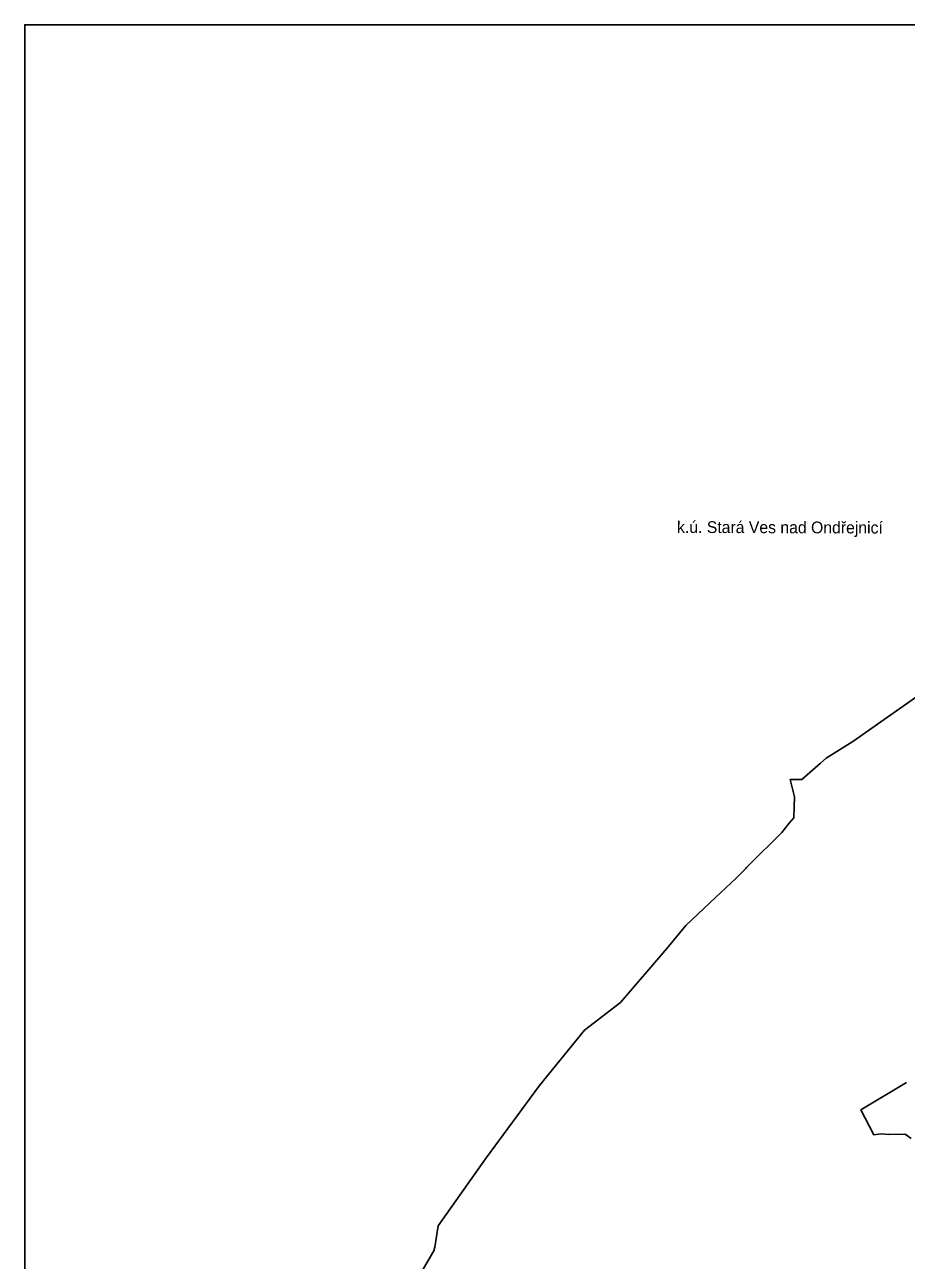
# Model space of a CAD drawing. Extents: x -478440 to -472455, y -1118045 to -1113755.
# Drawn here: x -478440 to -476944, y -1115899 to -1113800 of the extents above; entities that cross this region are included whole.
import ezdxf

# ---------------------------------------------------------------- set-up
doc = ezdxf.new("R2010")
doc.units = 0
for name, color, linetype in [('hranice kú', 7, 'Continuous'), ('Implicitní', 7, 'Continuous'), ('ObPÚ', 7, 'Continuous'), ('okolní k_ú_', 7, 'Continuous')]:
    doc.layers.add(name, color=color, linetype=linetype)

msp = doc.modelspace()

# ---------------------------------------------------------------- linework, layer by layer
at = {"layer": 'hranice kú'}
for p, q in [((-476889.8, -1114915.9), (-477034.1, -1115017.7)), ((-477034.1, -1115017.7), (-477047.8, -1115026.2)), ((-477047.8, -1115026.2), (-477079.5, -1115046.1)), ((-477098.4, -1115062.6), (-477121, -1115082.3)), ((-477089.2, -1115054.5), (-477098.4, -1115062.6)), ((-477079.5, -1115046.1), (-477089.2, -1115054.5)), ((-477121, -1115082.3), (-477141, -1115082)), ((-477141, -1115082), (-477133.6, -1115111.5)), ((-477133.6, -1115111.5), (-477134.2, -1115129.3)), ((-477134.7, -1115147.1), (-477142.3, -1115156.6)), ((-477134.2, -1115129.3), (-477134.7, -1115147.1)), ((-477142.3, -1115156.6), (-477155, -1115172.4)), ((-477155, -1115172.4), (-477210.7, -1115227.9)), ((-477210.7, -1115227.9), (-477214.6, -1115231.9)), ((-477233.1, -1115250.4), (-477267, -1115282.3)), ((-477229.4, -1115246.9), (-477233.1, -1115250.4)), ((-477216.6, -1115233.9), (-477229.4, -1115246.9)), ((-477214.6, -1115231.9), (-477216.6, -1115233.9)), ((-477267, -1115282.3), (-477317.9, -1115330.4)), ((-477317.9, -1115330.4), (-477350, -1115369.3)), ((-477350, -1115369.3), (-477428.5, -1115460.9)), ((-477428.5, -1115460.9), (-477490.1, -1115508.2)), ((-477490.1, -1115508.2), (-477566.2, -1115601.8)), ((-477566.2, -1115601.8), (-477658.2, -1115726.7)), ((-477658.2, -1115726.7), (-477738.5, -1115840.6)), ((-477738.5, -1115840.6), (-477743.9, -1115876.8)), ((-477743.9, -1115876.8), (-477745.7, -1115882.6)), ((-477745.7, -1115882.6), (-477792.7, -1115963.5))]:
    msp.add_line(p, q, dxfattribs=at)
at = {"layer": 'Implicitní'}
msp.add_lwpolyline([(-478440.1, -1118000.1), (-472500.1, -1118000.1), (-472500.1, -1113800.1), (-478440.1, -1113800.1)], close=True, dxfattribs=at)
at = {"layer": 'ObPÚ'}
for p, q in [((-476889.8, -1114915.9), (-477034.1, -1115017.7)), ((-477034.1, -1115017.7), (-477047.8, -1115026.2)), ((-477047.8, -1115026.2), (-477079.5, -1115046.1)), ((-477098.4, -1115062.6), (-477121, -1115082.3)), ((-477089.2, -1115054.5), (-477098.4, -1115062.6)), ((-477079.5, -1115046.1), (-477089.2, -1115054.5)), ((-477121, -1115082.3), (-477141, -1115082)), ((-477141, -1115082), (-477133.6, -1115111.5)), ((-477133.6, -1115111.5), (-477134.2, -1115129.3)), ((-477134.7, -1115147.1), (-477142.3, -1115156.6)), ((-477134.2, -1115129.3), (-477134.7, -1115147.1)), ((-477142.3, -1115156.6), (-477155, -1115172.4)), ((-477155, -1115172.4), (-477210.7, -1115227.9)), ((-477210.7, -1115227.9), (-477214.6, -1115231.9)), ((-477233.1, -1115250.4), (-477267, -1115282.3)), ((-477229.4, -1115246.9), (-477233.1, -1115250.4)), ((-477216.6, -1115233.9), (-477229.4, -1115246.9)), ((-477214.6, -1115231.9), (-477216.6, -1115233.9)), ((-477267, -1115282.3), (-477317.9, -1115330.4)), ((-477317.9, -1115330.4), (-477350, -1115369.3)), ((-477350, -1115369.3), (-477428.5, -1115460.9)), ((-477428.5, -1115460.9), (-477490.1, -1115508.2)), ((-477490.1, -1115508.2), (-477566.2, -1115601.8)), ((-477566.2, -1115601.8), (-477658.2, -1115726.7)), ((-477658.2, -1115726.7), (-477738.5, -1115840.6)), ((-477738.5, -1115840.6), (-477743.9, -1115876.8)), ((-477743.9, -1115876.8), (-477745.7, -1115882.6)), ((-477745.7, -1115882.6), (-477792.7, -1115963.5))]:
    msp.add_line(p, q, dxfattribs=at)
msp.add_lwpolyline([(-476935.6, -1115692.1), (-476945.3, -1115684.7), (-476973.5, -1115685.2), (-476986, -1115684.2), (-476998.5, -1115686), (-477020.9, -1115643.5), (-476943, -1115597.1)], dxfattribs=at)

# ---------------------------------------------------------------- texts
at = {"layer": 'okolní k_ú_'}
msp.add_text('k.ú. Stará Ves nad Ondřejnicí', height=20, rotation=359.8237, dxfattribs=at).set_placement((-477332.8, -1114663.3))

doc.saveas('drawing.dxf')
